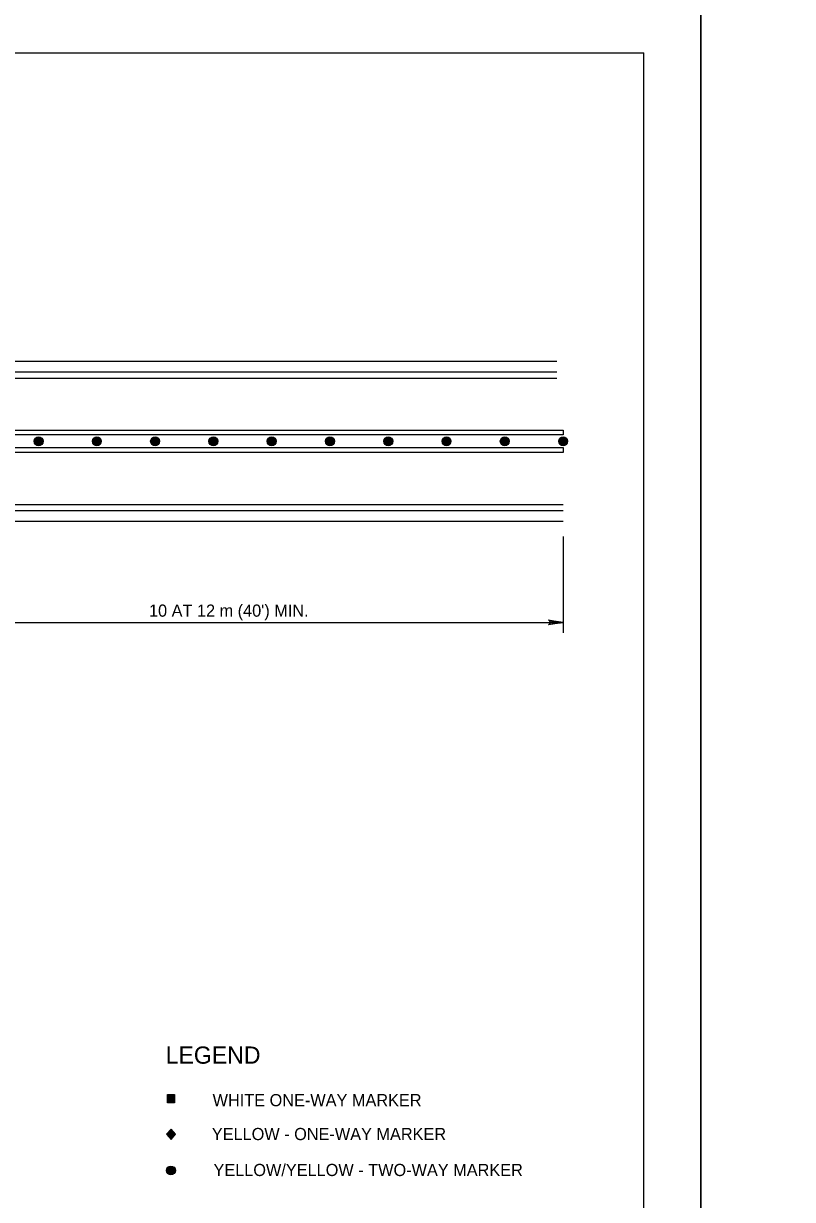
# Model space of a CAD drawing. Extents: x 639362 to 641108, y 298458 to 299646.
# Drawn here: x 640036.4 to 640225.9, y 298754.5 to 299044.4 of the extents above; entities that cross this region are included whole.
import ezdxf

# ---------------------------------------------------------------- set-up
doc = ezdxf.new("R2010")
doc.units = 0
for name, color, linetype in [('1', 7, 'Continuous'), ('2', 7, 'Continuous'), ('3', 7, 'Continuous'), ('PLT-BNDY', 7, 'Continuous')]:
    doc.layers.add(name, color=color, linetype=linetype)

# ---------------------------------------------------------------- blocks, each defined once
blk = doc.blocks.new('RARROW')
at = {"layer": '3'}
blk.add_lwpolyline([(-2.2695, 0.285), (-2.184875, 0.12075), (0, 0), (-2.2695, 0.285), (-2.38575, 0.384625), (0, 0), (-2.183125, -0.108), (-2.262875, -0.2705), (0, 0), (-2.38575, -0.379125), (-2.262875, -0.2705)], dxfattribs=at)

msp = doc.modelspace()

# ---------------------------------------------------------------- linework, layer by layer
at = {"layer": '1'}
for p in [(639403.27, 299037.19), (640189.27, 298473.19)]:
    msp.add_line(p, (640189.27, 299037.19), dxfattribs=at)
at = {"layer": '2'}
for p, q in [((640025.73, 298961.2), (640167.82, 298961.2)), ((640025.73, 298958.51), (640167.82, 298958.51)), ((640025.73, 298957.01), (640167.82, 298957.01)), ((640025.73, 298944.19), (640169.33, 298944.19)), ((640169.33, 298944.19), (640169.33, 298942.99)), ((640169.33, 298942.99), (640025.61, 298942.99)), ((640025.63, 298939.88), (640169.33, 298939.88)), ((640169.33, 298938.68), (640025.73, 298938.68)), ((640169.33, 298939.88), (640169.33, 298938.68)), ((640025.73, 298925.85), (640169.33, 298925.85)), ((640025.73, 298924.35), (640169.33, 298924.35)), ((640025.73, 298921.72), (640169.33, 298921.72)), ((640169.35, 298917.97), (640169.35, 298894.23)), ((640025.73, 298896.78), (640169.33, 298896.78)), ((640071.82, 298780.37), (640073.59, 298780.37)), ((640071.82, 298778.33), (640071.82, 298780.37)), ((640073.59, 298778.33), (640071.82, 298778.33)), ((640072, 298780.19), (640073.41, 298780.19)), ((640072, 298778.51), (640072, 298780.19)), ((640073.41, 298778.51), (640072, 298778.51)), ((640072.17, 298780.01), (640073.24, 298780.01)), ((640072.17, 298778.68), (640072.17, 298780.01)), ((640073.24, 298778.68), (640072.17, 298778.68)), ((640072.35, 298778.86), (640072.35, 298779.83)), ((640072.35, 298779.83), (640073.06, 298779.83)), ((640073.06, 298778.86), (640072.35, 298778.86)), ((640072.53, 298779.66), (640072.88, 298779.66)), ((640072.53, 298779.04), (640072.53, 298779.66)), ((640072.88, 298779.04), (640072.53, 298779.04)), ((640072.7, 298779.48), (640072.7, 298779.21)), ((640072.88, 298779.66), (640072.88, 298779.04)), ((640073.06, 298779.83), (640073.06, 298778.86)), ((640073.24, 298780.01), (640073.24, 298778.68)), ((640073.41, 298780.19), (640073.41, 298778.51)), ((640073.59, 298780.37), (640073.59, 298778.33)), ((640072.73, 298771.89), (640071.6, 298770.59)), ((640071.6, 298770.59), (640072.73, 298769.3)), ((640071.6, 298770.59), (640073.86, 298770.59)), ((640071.71, 298770.71), (640072.84, 298769.42)), ((640072.84, 298771.77), (640071.72, 298770.49)), ((640072.94, 298771.65), (640071.81, 298770.35)), ((640071.81, 298770.83), (640072.94, 298769.54)), ((640073.04, 298771.53), (640071.92, 298770.23)), ((640071.92, 298770.95), (640073.04, 298769.66)), ((640073.15, 298771.41), (640072.02, 298770.11)), ((640072.02, 298771.07), (640073.15, 298769.78)), ((640073.25, 298771.29), (640072.13, 298769.99)), ((640072.13, 298771.19), (640073.25, 298769.9)), ((640072.23, 298771.31), (640073.36, 298770.02)), ((640073.36, 298771.17), (640072.23, 298769.87)), ((640072.33, 298771.43), (640073.46, 298770.14)), ((640073.46, 298771.05), (640072.33, 298769.75)), ((640072.44, 298771.55), (640073.57, 298770.26)), ((640073.57, 298770.93), (640072.44, 298769.63)), ((640072.54, 298771.67), (640073.67, 298770.38)), ((640073.67, 298770.81), (640072.54, 298769.51)), ((640072.65, 298771.79), (640073.78, 298770.5)), ((640073.78, 298770.69), (640072.65, 298769.4)), ((640073.86, 298770.59), (640072.73, 298771.89)), ((640072.73, 298771.89), (640072.73, 298769.3)), ((640072.73, 298769.3), (640073.86, 298770.59))]:
    msp.add_line(p, q, dxfattribs=at)
for centre, radius in [((640040.09, 298941.43), 1.1), ((640040.09, 298941.43), 1.02), ((640040.09, 298941.43), 0.946), ((640040.09, 298941.43), 0.868), ((640040.09, 298941.43), 0.789), ((640040.09, 298941.43), 0.711), ((640040.09, 298941.43), 0.633), ((640040.09, 298941.43), 0.554), ((640040.09, 298941.43), 0.476), ((640040.09, 298941.43), 0.398), ((640040.09, 298941.43), 0.32), ((640040.09, 298941.43), 0.241), ((640040.09, 298941.43), 0.163), ((640040.09, 298941.43), 0.0846), ((640054.45, 298941.43), 1.1), ((640054.45, 298941.43), 1.02), ((640054.45, 298941.43), 0.946), ((640054.45, 298941.43), 0.868), ((640054.45, 298941.43), 0.789), ((640054.45, 298941.43), 0.711), ((640054.45, 298941.43), 0.633), ((640054.45, 298941.43), 0.554), ((640054.45, 298941.43), 0.476), ((640054.45, 298941.43), 0.398), ((640054.45, 298941.43), 0.32), ((640054.45, 298941.43), 0.241), ((640054.45, 298941.43), 0.163), ((640054.45, 298941.43), 0.0846), ((640068.81, 298941.43), 1.1), ((640068.81, 298941.43), 1.02), ((640068.81, 298941.43), 0.946), ((640068.81, 298941.43), 0.868), ((640068.81, 298941.43), 0.789), ((640068.81, 298941.43), 0.711), ((640068.81, 298941.43), 0.633), ((640068.81, 298941.43), 0.554), ((640068.81, 298941.43), 0.476), ((640068.81, 298941.43), 0.398), ((640068.81, 298941.43), 0.32), ((640068.81, 298941.43), 0.241), ((640068.81, 298941.43), 0.163), ((640068.81, 298941.43), 0.0846), ((640083.17, 298941.43), 1.1), ((640083.17, 298941.43), 1.02), ((640083.17, 298941.43), 0.946), ((640083.17, 298941.43), 0.868), ((640083.17, 298941.43), 0.789), ((640083.17, 298941.43), 0.711), ((640083.17, 298941.43), 0.633), ((640083.17, 298941.43), 0.554), ((640083.17, 298941.43), 0.476), ((640083.17, 298941.43), 0.398), ((640083.17, 298941.43), 0.32), ((640083.17, 298941.43), 0.241), ((640083.17, 298941.43), 0.163), ((640083.17, 298941.43), 0.0846), ((640097.53, 298941.43), 1.1), ((640097.53, 298941.43), 1.02), ((640097.53, 298941.43), 0.946), ((640097.53, 298941.43), 0.868), ((640097.53, 298941.43), 0.789), ((640097.53, 298941.43), 0.711), ((640097.53, 298941.43), 0.633), ((640097.53, 298941.43), 0.554), ((640097.53, 298941.43), 0.476), ((640097.53, 298941.43), 0.398), ((640097.53, 298941.43), 0.32), ((640097.53, 298941.43), 0.241), ((640097.53, 298941.43), 0.163), ((640097.53, 298941.43), 0.0846), ((640111.89, 298941.43), 1.1), ((640111.89, 298941.43), 1.02), ((640111.89, 298941.43), 0.946), ((640111.89, 298941.43), 0.868), ((640111.89, 298941.43), 0.789), ((640111.89, 298941.43), 0.711), ((640111.89, 298941.43), 0.633), ((640111.89, 298941.43), 0.554), ((640111.89, 298941.43), 0.476), ((640111.89, 298941.43), 0.398), ((640111.89, 298941.43), 0.32), ((640111.89, 298941.43), 0.241), ((640111.89, 298941.43), 0.163), ((640111.89, 298941.43), 0.0846), ((640126.25, 298941.43), 1.1), ((640126.25, 298941.43), 1.02), ((640126.25, 298941.43), 0.946), ((640126.25, 298941.43), 0.868), ((640126.25, 298941.43), 0.789), ((640126.25, 298941.43), 0.711), ((640126.25, 298941.43), 0.633), ((640126.25, 298941.43), 0.554), ((640126.25, 298941.43), 0.476), ((640126.25, 298941.43), 0.398), ((640126.25, 298941.43), 0.32), ((640126.25, 298941.43), 0.241), ((640126.25, 298941.43), 0.163), ((640126.25, 298941.43), 0.0846), ((640140.61, 298941.43), 1.1), ((640140.61, 298941.43), 1.02), ((640140.61, 298941.43), 0.946), ((640140.61, 298941.43), 0.868), ((640140.61, 298941.43), 0.789), ((640140.61, 298941.43), 0.711), ((640140.61, 298941.43), 0.633), ((640140.61, 298941.43), 0.554), ((640140.61, 298941.43), 0.476), ((640140.61, 298941.43), 0.398), ((640140.61, 298941.43), 0.32), ((640140.61, 298941.43), 0.241), ((640140.61, 298941.43), 0.163), ((640140.61, 298941.43), 0.0846), ((640154.97, 298941.43), 1.1), ((640154.97, 298941.43), 1.02), ((640154.97, 298941.43), 0.946), ((640154.97, 298941.43), 0.868), ((640154.97, 298941.43), 0.789), ((640154.97, 298941.43), 0.711), ((640154.97, 298941.43), 0.633), ((640154.97, 298941.43), 0.554), ((640154.97, 298941.43), 0.476), ((640154.97, 298941.43), 0.398), ((640154.97, 298941.43), 0.32), ((640154.97, 298941.43), 0.241), ((640154.97, 298941.43), 0.163), ((640154.97, 298941.43), 0.0846), ((640169.35, 298941.43), 1.1), ((640169.35, 298941.43), 1.02), ((640169.35, 298941.43), 0.946), ((640169.35, 298941.43), 0.868), ((640169.35, 298941.43), 0.789), ((640169.35, 298941.43), 0.711), ((640169.35, 298941.43), 0.633), ((640169.35, 298941.43), 0.554), ((640169.35, 298941.43), 0.476), ((640169.35, 298941.43), 0.398), ((640169.35, 298941.43), 0.32), ((640169.35, 298941.43), 0.241), ((640169.35, 298941.43), 0.163), ((640169.35, 298941.43), 0.0846), ((640072.7, 298761.68), 1.1), ((640072.7, 298761.68), 1.02), ((640072.7, 298761.68), 0.946), ((640072.7, 298761.68), 0.868), ((640072.7, 298761.68), 0.789), ((640072.7, 298761.68), 0.711), ((640072.7, 298761.68), 0.633), ((640072.7, 298761.68), 0.554), ((640072.7, 298761.68), 0.476), ((640072.7, 298761.68), 0.398), ((640072.7, 298761.68), 0.32), ((640072.7, 298761.68), 0.241), ((640072.7, 298761.68), 0.163), ((640072.7, 298761.68), 0.0846)]:
    msp.add_circle(centre, radius, dxfattribs=at)
at = {"layer": 'PLT-BNDY'}
for points in [[(639362.31, 299051.63), (640203.31, 299051.63), (640203.31, 298457.63), (639362.31, 298457.63)], [(640203.31, 299051.63), (641044.31, 299051.63), (641044.31, 298457.63), (640203.31, 298457.63)]]:
    msp.add_lwpolyline(points, close=True, dxfattribs=at)

# ---------------------------------------------------------------- block references
at = {"layer": '2', "xscale": 1.5089217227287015, "yscale": 1.5711553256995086}
msp.add_blockref('RARROW', (640169.33, 298896.78), dxfattribs=at)

# ---------------------------------------------------------------- texts
at = {"layer": '2'}
for s, height, p in [("10 AT 12 m (40') MIN.", 3, (640067.3, 298898.19)), ('LEGEND', 4.25, (640071.4, 298788)), ('WHITE ONE-WAY MARKER', 3, (640082.98, 298777.52)), ('YELLOW - ONE-WAY MARKER', 3, (640082.78, 298769.17)), ('YELLOW/YELLOW - TWO-WAY MARKER', 3, (640083.19, 298760.31))]:
    msp.add_text(s, height=height, dxfattribs=at).set_placement(p)

doc.saveas('drawing.dxf')
